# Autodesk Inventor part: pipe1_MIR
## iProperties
Shininess: 64.0
Length Units: 11272
Angle Units: 11279
Time Units: 11290
Mass Units: 11286
Length Display Precision: 3
Angle Display Precision: 2
Compacted: True
Part Number: pipe1_MIR
Document SubType Name: Modeling
Created: 2004-08
Designer: John Blackburn
Material: Default
Manufacturer: Standard
Standards Organization: Custom
Density: 0.0
Volumn: 0.0
Area: 0.0
PropertySet Name: Model Information
Control State: 0
Master: False
Checked Out: False
Author: John Blackburn
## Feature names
1. Derived Body1 [Tagging]
